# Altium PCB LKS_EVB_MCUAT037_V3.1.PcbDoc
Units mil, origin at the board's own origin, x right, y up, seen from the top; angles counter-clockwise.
Board outline 944.88 x 787.4 mil, 2 copper layers (Top Layer, Bottom Layer); 21 components, 22 nets, 69 pads, 26 vias.
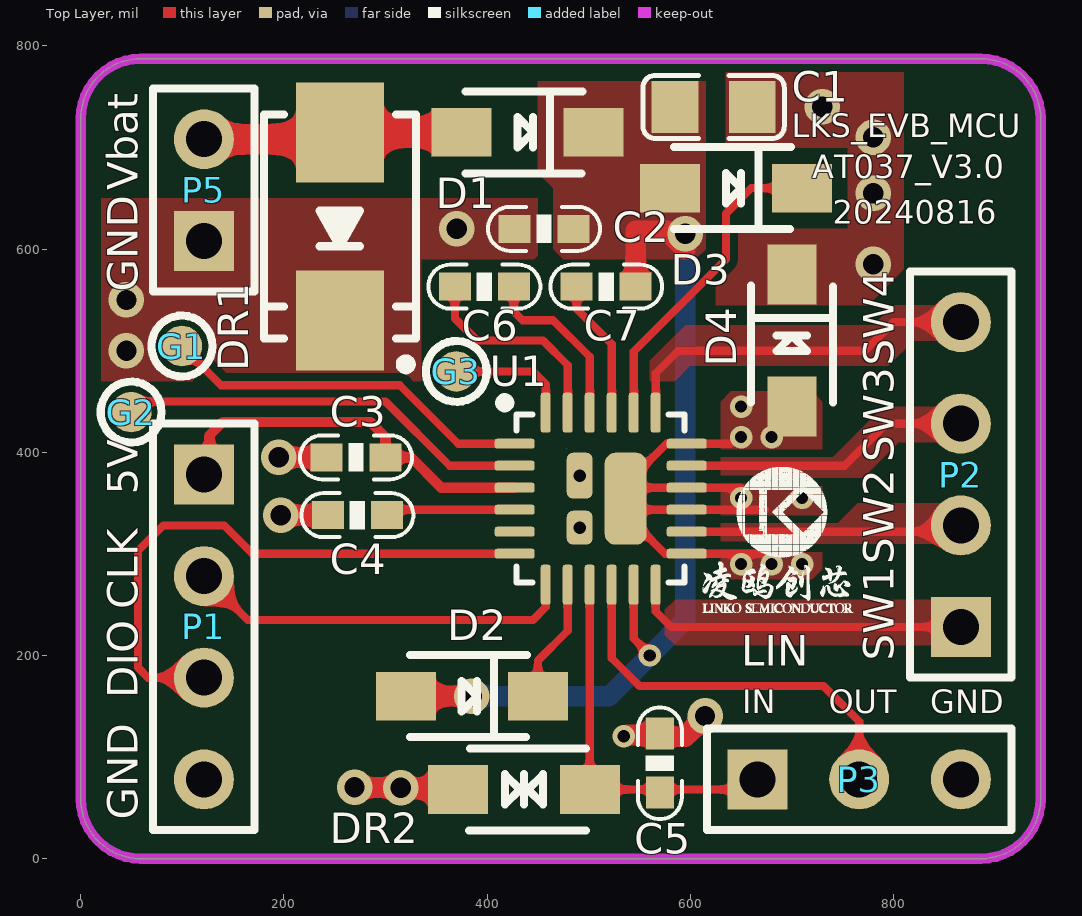
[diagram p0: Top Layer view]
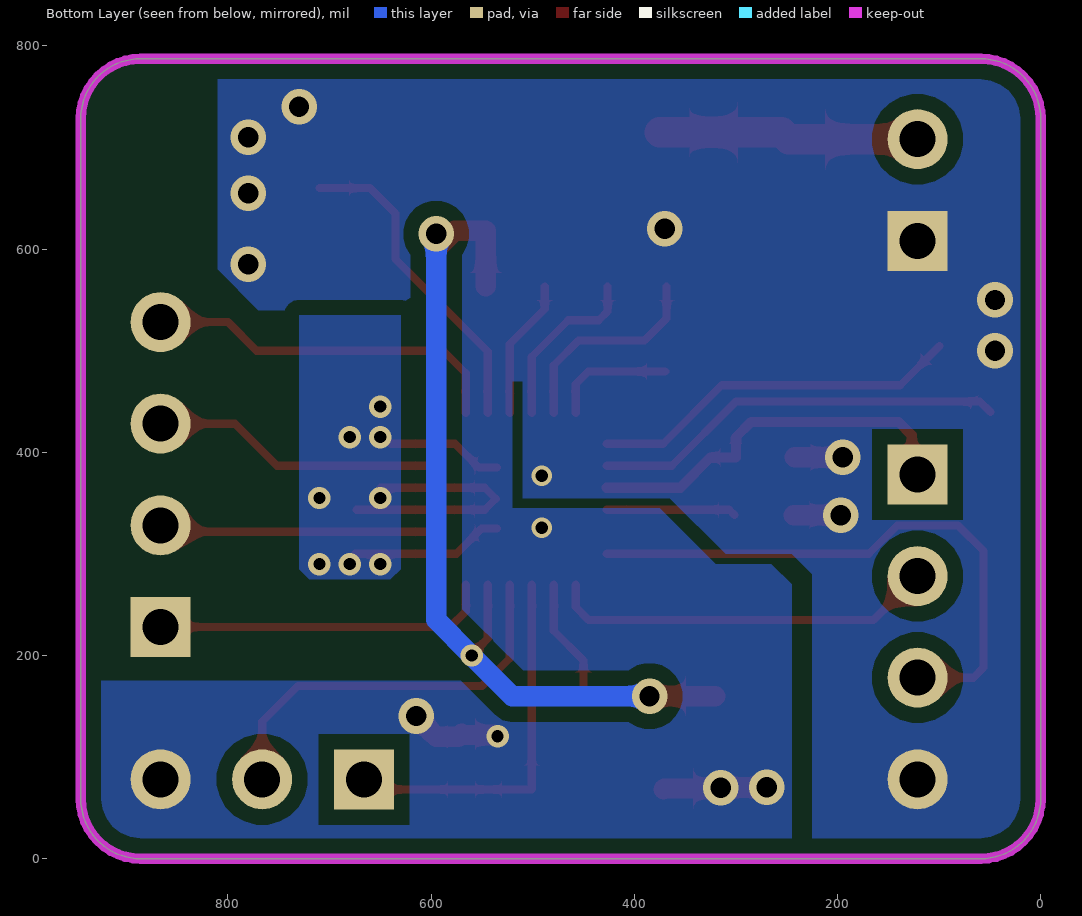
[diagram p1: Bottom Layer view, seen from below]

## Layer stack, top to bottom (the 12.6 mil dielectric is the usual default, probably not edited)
Top Solder: solder mask 0.4, Solder Resist, Dk 3.5
Top Layer: signal copper 1.4
Dielectric 1: dielectric 12.6, FR-4, Dk 4.8
Bottom Layer: signal copper 1.4
Bottom Solder: solder mask 0.4, Solder Resist, Dk 3.5

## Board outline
59.06,0 cw(c59.06,59.06) 0,59.06 0,728.35 cw(c59.06,728.35) 59.06,787.4 885.83,787.4 cw(c885.83,728.35) 944.88,728.35 944.88,59.06 cw(c885.83,59.06) 885.83,0

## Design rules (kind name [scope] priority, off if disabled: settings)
Clearance Clearance_1 [All vs OnLayer('Bottom Layer')] p1: gap=15 ignorepadtopadclearanceinfootprint=FALSE
Clearance [All] p2: gap=8 ignorepadtopadclearanceinfootprint=FALSE
ComponentClearance [All] p1: gap=0 collisioncheckmode=3 verticalgap=0 showdistances=FALSE
HoleToHoleClearance [All] p1: gap=0 allowstackedmicrovias=TRUE
MinimumSolderMaskSliver [All] p1: minsoldermaskwidth=0
PolygonConnect [All] p1: connectstyle=Direct reliefconductorwidth=10 reliefentries=4 polygonreliefangle="90 Angle" airgapwidth=10
RoutingVias [All] p1: holewidth=28 width=50 viastyle="Through Hole" minholewidth=0 minwidth=0 maxholewidth=50 maxwidth=100
SilkToSilkClearance [All] p1: silktosilkclearance=0
SilkToSolderMaskClearance [IsPad] p1: minsilkscreentomaskgap=0 clearancetoexposedcopper=TRUE
SolderMaskExpansion [All] p1: expansion=4 istentingtop=FALSE
Width [All] p1: maxlimit=80 minlimit=5 preferedwidth=10
25 further rules are at their usual default settings.

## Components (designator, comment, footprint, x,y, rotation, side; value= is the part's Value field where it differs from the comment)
C1 "4.7uF/50V" 0805C 623,740 r0 top
C2 "100nF/50V" 0603C 456,620 r180 top
C3 "1uF/16V" 0603C 270.94,395 r0 top
C4 "100nF/50V" 0603C 272.26,338.15 r180 top
C5 "220pF/50V" 0603C 570,94 r90 top
C6 "22nF/100V" 0603C 397.26,563.15 r180 top
C7 "1uF/50V" 0603C 517.2,563.15 r0 top
D1 "S2MW" SOD-123 439.96,715 r0 top
D2 "S2MW" SOD-123 385,160 r0 top
D3 "S2MW" SOD-123 644.96,660 r0 top
D4 "S2MW" SOD-123 700,509.96 r90 top
DR1 "SMAJ33CA" SMB 255,622.48 r270 top
DR2 "SMF24CA" SOD-123F 436.3,68.15 r180 top
G1 "PAD1.2" TP-40 100,505 r0 top
G2 "PAD1.2" TP-40 50,440 r0 top
G3 "PAD1.2" TP-40 370,480 r0 top
P1 "Header 4" "HDR 1X4" 121.26,378.15 r270 top
P2 "HDR-1X4" "HDR 1X4" 866.26,228.15 r90 top
P3 "1X3" "HDR 1X3" 666.26,78.15 r0 top
P5 "B2P-VH(LF)(SN)" "HDR 1X2" 121.26,608.15 r90 top
U1 "LKS32AT037PXL5M6Q9" QFN24-0.55mm 511.81,354.33 r270 top locked

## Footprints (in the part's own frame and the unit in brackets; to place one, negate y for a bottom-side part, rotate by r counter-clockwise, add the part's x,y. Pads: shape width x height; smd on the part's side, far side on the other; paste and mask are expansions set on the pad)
0603C [mm] "电容"
  rect 0.8x0.7 smd: 1(-0.737,0) 2(0.738,0)
  silkscreen extent -1.4,-0.55 1.4,0.55, body extent -0.8,-0.41 0.8,0.41, height 0.81
0805C [mil] "电容"
  rect 46x51.18 smd: 1(-38,0) 2(38,0)
  silkscreen extent -69,-31 70,31, body extent -39,-24 39,24, height 20
"HDR 1X2" [mm] "单排针 2.54mm"
  rect 1.5x1.5 hole 0.9: 1(0,0)
  round 1.5 hole 0.9: 2(2.54,0)
  silkscreen extent -1.27,-1.27 3.81,1.27, body extent -1.27,-1.27 3.81,1.27, height 8.5
"HDR 1X3" [mm] "单排针 2.54mm"
  rect 1.5x1.5 hole 0.9: 1(0,0)
  round 1.5 hole 0.9: 2(2.54,0) 3(5.08,0)
  silkscreen extent -1.27,-1.27 6.35,1.27, body extent -1.27,-1.27 6.35,1.27, height 8.5
"HDR 1X4" [mm] "排针-单 2.54mm"
  rect 1.5x1.5 hole 0.9: 1(0,0)
  round 1.5 hole 0.9: 2(2.54,0) 3(5.08,0) 4(7.62,0)
  silkscreen extent -1.27,-1.27 8.89,1.27, body extent -1.27,-1.27 8.89,1.27, height 8.5
QFN24-0.55mm [mm] "4mm*4mm"
  rrect50% 1.15x0.65 smd: 0(-0.575,-0.525)
  rrect50% 0.25x1 smd: 1(-1.375,-2.15) 2(-0.825,-2.15) 3(-0.275,-2.15) 4(0.275,-2.15) 5(0.825,-2.15) 6(1.375,-2.15) 13(1.375,2.15) 14(0.825,2.15) 15(0.275,2.15) 16(-0.275,2.15) 17(-0.825,2.15) 18(-1.375,2.15)
  rrect50% 1x0.25 smd: 7(2.15,-1.375) 8(2.15,-0.825) 9(2.15,-0.275) 10(2.15,0.275) 11(2.15,0.825) 12(2.15,1.375) 19(-2.15,1.375) 20(-2.15,0.825) 21(-2.15,0.275) 22(-2.15,-0.275) 23(-2.15,-0.825) 24(-2.15,-1.375)
  rrect50% 0.85x0.65 smd: 25(0.725,-0.525)
  rrect50% 2.3x1.05 smd: 26(0,0.625)
  silkscreen extent -2.51,-2.51 2.1,2.1, body extent -2.01,-2.01 2.01,2.01, height 0.95
SMB [mm] "二极管"
  rect 2.5x2.2 smd: 1(-2.35,0) 2(2.35,0)
  silkscreen extent -2.8,-1.9 3.57,1.9, body extent -2.63,-1.8 2.67,1.8, height 2.35
SOD-123 [mm] "二极管"
  rect 1.5x1.22 smd: 1(-1.65,0) 2(1.65,0)
  silkscreen extent -1.55,-1.03 1.38,1.02, body extent -1.85,-0.8 1.85,0.8, height 1.22
SOD-123F [mm] "双向TVS管"
  rect 1.5x1.22 smd: 1(-1.65,0) 2(1.65,0)
  silkscreen extent -1.55,-1.03 1.38,1.02, body extent -1.85,-0.8 1.85,0.8, height 1.22
TP-40 [mil] "测试点"
  round 40 smd: 1(-0.39,-0.39)
  silkscreen extent -30,-30 30,30

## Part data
C1 C2 C5 C6 C7: library part Capacitor, "Capacitor --贴片电容"
C3 C4: library part C, "Capacitor"
D1 D2 D3 D4: library part 1N4148, "高速开关二极管"
DR1: library part DR, "瞬态电压抑制二极管   极性：双向 反向截止电压(Vrwm)：24V 击穿电压：26.7V 反向漏电流(Ir)：1uA 峰值脉冲电流(Ipp)@10/1000μs：15.5A 最大钳位电压：38.9V TVS瞬态抑制二极管@10/1000μs：11.3A 最大钳位电压：53.3V"
DR2: library part "TVS 双向", "JLC-C5333993"
G1 G2 G3: "焊盘"
P1: "Header, 4-Pin"
P2: library part "Header 4", "Header, 4-Pin"
P3: "单排针"
P5: library part "Header 2", "2P接插件"
U1: "芯片"

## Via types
v1: diameter 35, hole 20, Top Layer to Bottom Layer, 14 vias
v2: diameter 22, hole 12, Top Layer to Bottom Layer, 10 vias
v3: diameter 20, hole 12, Top Layer to Bottom Layer, 2 vias

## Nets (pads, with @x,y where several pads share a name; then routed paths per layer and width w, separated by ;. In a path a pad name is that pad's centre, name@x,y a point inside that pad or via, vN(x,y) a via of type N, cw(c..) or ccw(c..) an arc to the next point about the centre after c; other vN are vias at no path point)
+5V: C3.2 P1.1 U1.3 | length 385.4
  Top Layer w10: P1.1 126.82,383.71 126.82,416.82 140,430 285,430 300,415 C3.2 325,395 354.84,365.16 U1.3
CN: C6.2 U1.23 | length 208.3
  Top Layer w8: C6.2 368.2,531.8 390,510 455,510 479.33,485.67 U1.23
CP: C6.1 U1.22 | length 172.7
  Top Layer w8: C6.1 426.26,538.74 435,530 465,530 500.98,494.02 U1.22
GND: C1.2 C2.2 C3.1 C4.2 C5.2 D4.2 DR1.2 DR2.2 P1.4 P3.3 P5.1 U1.0 U1.25 | length 286.5
  Top Layer w20: v1(195,395) C3.1 ; v1(196.85,338.15) C4.2 ; v1@270,70 v1(315,70) 315.93,69.07 370.41,69.07 DR2.2 ; v2(534.54,120.46) 535.83,121.76 568.7,121.76 C5.2 573.06,120 595,120 v1@615,140
  other v1: 269.54,70.46 614.54,140.46 45,500 45,550 780,585 370,620 780,655 780,710 730,740
  other v3: 491.14,325.79 491.14,376.97
LIN_IN: C5.1 DR2.1 P3.1 U1.9 | length 370.8
  Top Layer w8: U1.9 500.98,68.43 DR2.1 656.26,68.15 P3.1
LIN_OUT: P3.2 U1.10 | length 398.6
  Top Layer w8: U1.10 522.64,197.36 550,170 731.26,170 766.26,135 P3.2
NetD1_1: D1.1 DR1.1 P5.2 | length 256.6
  Top Layer w30: P5.2 248.15,708.15 DR1.1 D1.1
NetD2_2: D2.2 U1.8 | length 121.9
  Top Layer w8: D2.2 449.96,194.96 479.33,224.33 U1.8
NetD3_2: D3.2 U1.20 | length 318.9
  Top Layer w8: U1.20 544.29,499.29 635,590 635,635 660,660 D3.2
NRST: C4.1 U1.4 | length 128.1
  Top Layer w8: C4.1 306.61,343.5 U1.4
P0.9: G2.1 U1.2 | length 408
  Top Layer w8: G2.1 60,450 300,450 363.19,386.81 U1.2
P0.11: G1.1 U1.1 | length 367.4
  Top Layer w8: G1.1 138.21,466 314,466 371.54,408.46 U1.1
P1.5: G3.1 U1.24 | length 121.5
  Top Layer w8: G3.1 445.39,479.61 457.68,467.32 U1.24
PGND: D4.1 U1.13 U1.15 U1.16 U1.18 U1.26 | length 537.1
  Top Layer w8: U1.26@535,325 550.39,325 575.2,300.2 U1.13 674.8,300.2 ; U1.26@535,385 553.11,385 576.57,408.46 U1.18 639.68,408.46 646.21,415 v2(650,415) ; v2@650,365.16 U1.16 547.24,365.16 U1.26 547.24,343.5 U1.15 673.5,343.5
  other v2: 650,290 680,290 710,290 650,355 710,355 680,415 650,445
SW1: P2.1 U1.12 | length 332.9
  Top Layer w8: U1.12 565.94,243.46 581.26,228.15 P2.1
SW2: P2.2 U1.14 | length 272.4
  Top Layer w8: U1.14 859.96,321.85 P2.2
SW3: P2.3 U1.17 | length 286.9
  Top Layer w8: U1.17 751.81,386.81 793.15,428.15 P2.3
SW4: P2.4 U1.19 | length 360
  Top Layer w8: U1.19 565.94,477.83 588.11,500 771.85,500 800,528.15 P2.4
SWCLK: P1.2 U1.7 | length 381.5
  Top Layer w8: P1.2 164.41,235 445,235 457.68,247.68 U1.7
SWDIO: P1.3 U1.6 | length 577
  Top Layer w8: P1.3 66.26,178.15 56.26,188.15 56.26,303.15 81.26,328.15 141.26,328.15 169.21,300.2 U1.6
Vbat: C1.1 C2.1 C7.2 D1.2 D2.1 D3.1 U1.11 | length 876.3
  Top Layer w8: U1.11 544.29,216.82 560,201.11 v2(560,200)
  Top Layer w10: C7.2@544.29,561.18 C7.2
  Top Layer w20: D2.1 v1(385,160) ; C7.2 546.26,618.15 576.85,618.15 v1@595,600
  Bottom Layer w20: v1(385,160) 520,160 v2(560,200) 595,235 v1(595,615)
VCP: C7.1 U1.21 | length 138.4
  Top Layer w8: C7.1 488.2,541.2 522.64,506.77 U1.21
pads on no net: U1.5

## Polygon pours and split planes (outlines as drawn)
GND on Top Layer "10" (solid, remove dead copper, pour order 15): 625,545 775,545 810,580 810,790 635,790 635,700 755,700 755,620 642.5,620 635,612.5 635,590 625,580
SW4 on Top Layer "10" (solid, remove dead copper, pour order 5): 560,470 560,490 595,525 780,525 800,545 865,545 875,535 875,520 865,510 820,510 795,485 600,485 585,470
GND on Top Layer "10" (solid, remove dead copper, pour order 7): 20,650 140,650 290,650 450,650 450,590 335,590 335,470 20,470
Vbat on Top Layer "10" (solid, remove dead copper, pour order 9): 450,765 450,675 465,660 465,600 475,590 605,590 615,600 615,765
PGND on Top Layer "10" (solid, remove dead copper, pour order 0): 630,285 640,275 720,275 730,285 730,450 720,460 640,460 630,450
SW3 on Top Layer "10" (solid, remove dead copper, pour order 4): 630,375 630,395 740,395 790,445 860,445 875,430 875,415 865,405 860,410 805,410 770,375
SW2 on Top Layer "10" (solid, remove dead copper, pour order 3): 630,310 630,330 745,330 765,350 880,350 885,345 885,320 875,310
SW1 on Top Layer "10" (solid, remove dead copper, pour order 2): 575,245 575,220 585,210 870,210 880,220 880,240 865,255 585,255
GND on Bottom Layer "10" (solid, remove dead copper, pour order 14): 470,345 520,345 520,445 520,450 520,455 520,495 550,495 570,475 570,170 475,170 470,165
GND on Bottom Layer "10" (solid, remove dead copper, pour order 13): 510,355 510,490 0,490 0,0 225,0 225,280 245,300 310,300 365,355
GND on Bottom Layer "10" (solid, remove dead copper, pour order 12): 510,345 375,345 320,290 265,290 245,270 245,0 940,0 945,5 945,175 525,175 510,190
GND on Bottom Layer "10" (solid, remove dead copper, pour order 11): 0,790 0,470 575,470 595,490 595,525 610,540 770,540 810,580 810,790
PGND on Bottom Layer "10" (solid, remove dead copper, pour order 8): 630,285 640,275 720,275 730,285 730,535 630,535

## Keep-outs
Keep-Out Layer:
  the board outline again, w10

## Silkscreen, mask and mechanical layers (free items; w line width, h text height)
Top Overlay:
  drawing of 144 lines, arcs and shapes, not listed
  text "LKS_EVB_MCU" at 700,710 h23
  text "AT037_V3.0" at 720,670 h23
  text "Vbat" at 56.26,658.15 h30 r90
  text "20240816" at 740,625 h23
  text "GND" at 56.26,558.15 h30 r90
  text "SW4" at 800,485 h30 r90
  text "SW3" at 800,390 h30 r90
  text "5V" at 56.26,358.15 h30 r90
  text "SW2" at 800,290 h30 r90
  text "CLK" at 56.26,245.65 h30 r90
  text "SW1" at 800,195 h30 r90
  text "LIN" at 650,190 h30
  text "DIO" at 56.26,158.15 h30 r90
  text "IN" at 651.26,143.15 h23
  text "OUT" at 736.26,143.15 h23
  text "GND" at 836.26,143.15 h23
  text "GND" at 56.26,38.15 h30 r90

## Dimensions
885.83,787.4 to 885.83,0 on Top Overlay
0,728.35 to 944.88,728.35 on Top Overlay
